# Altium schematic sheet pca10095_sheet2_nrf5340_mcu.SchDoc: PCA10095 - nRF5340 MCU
size A3; Organization: Nordic Semiconductor; DocumentNumber: 2; SheetNumber: 2; SheetTotal: 6; CompanyName: Nordic Semiconductor
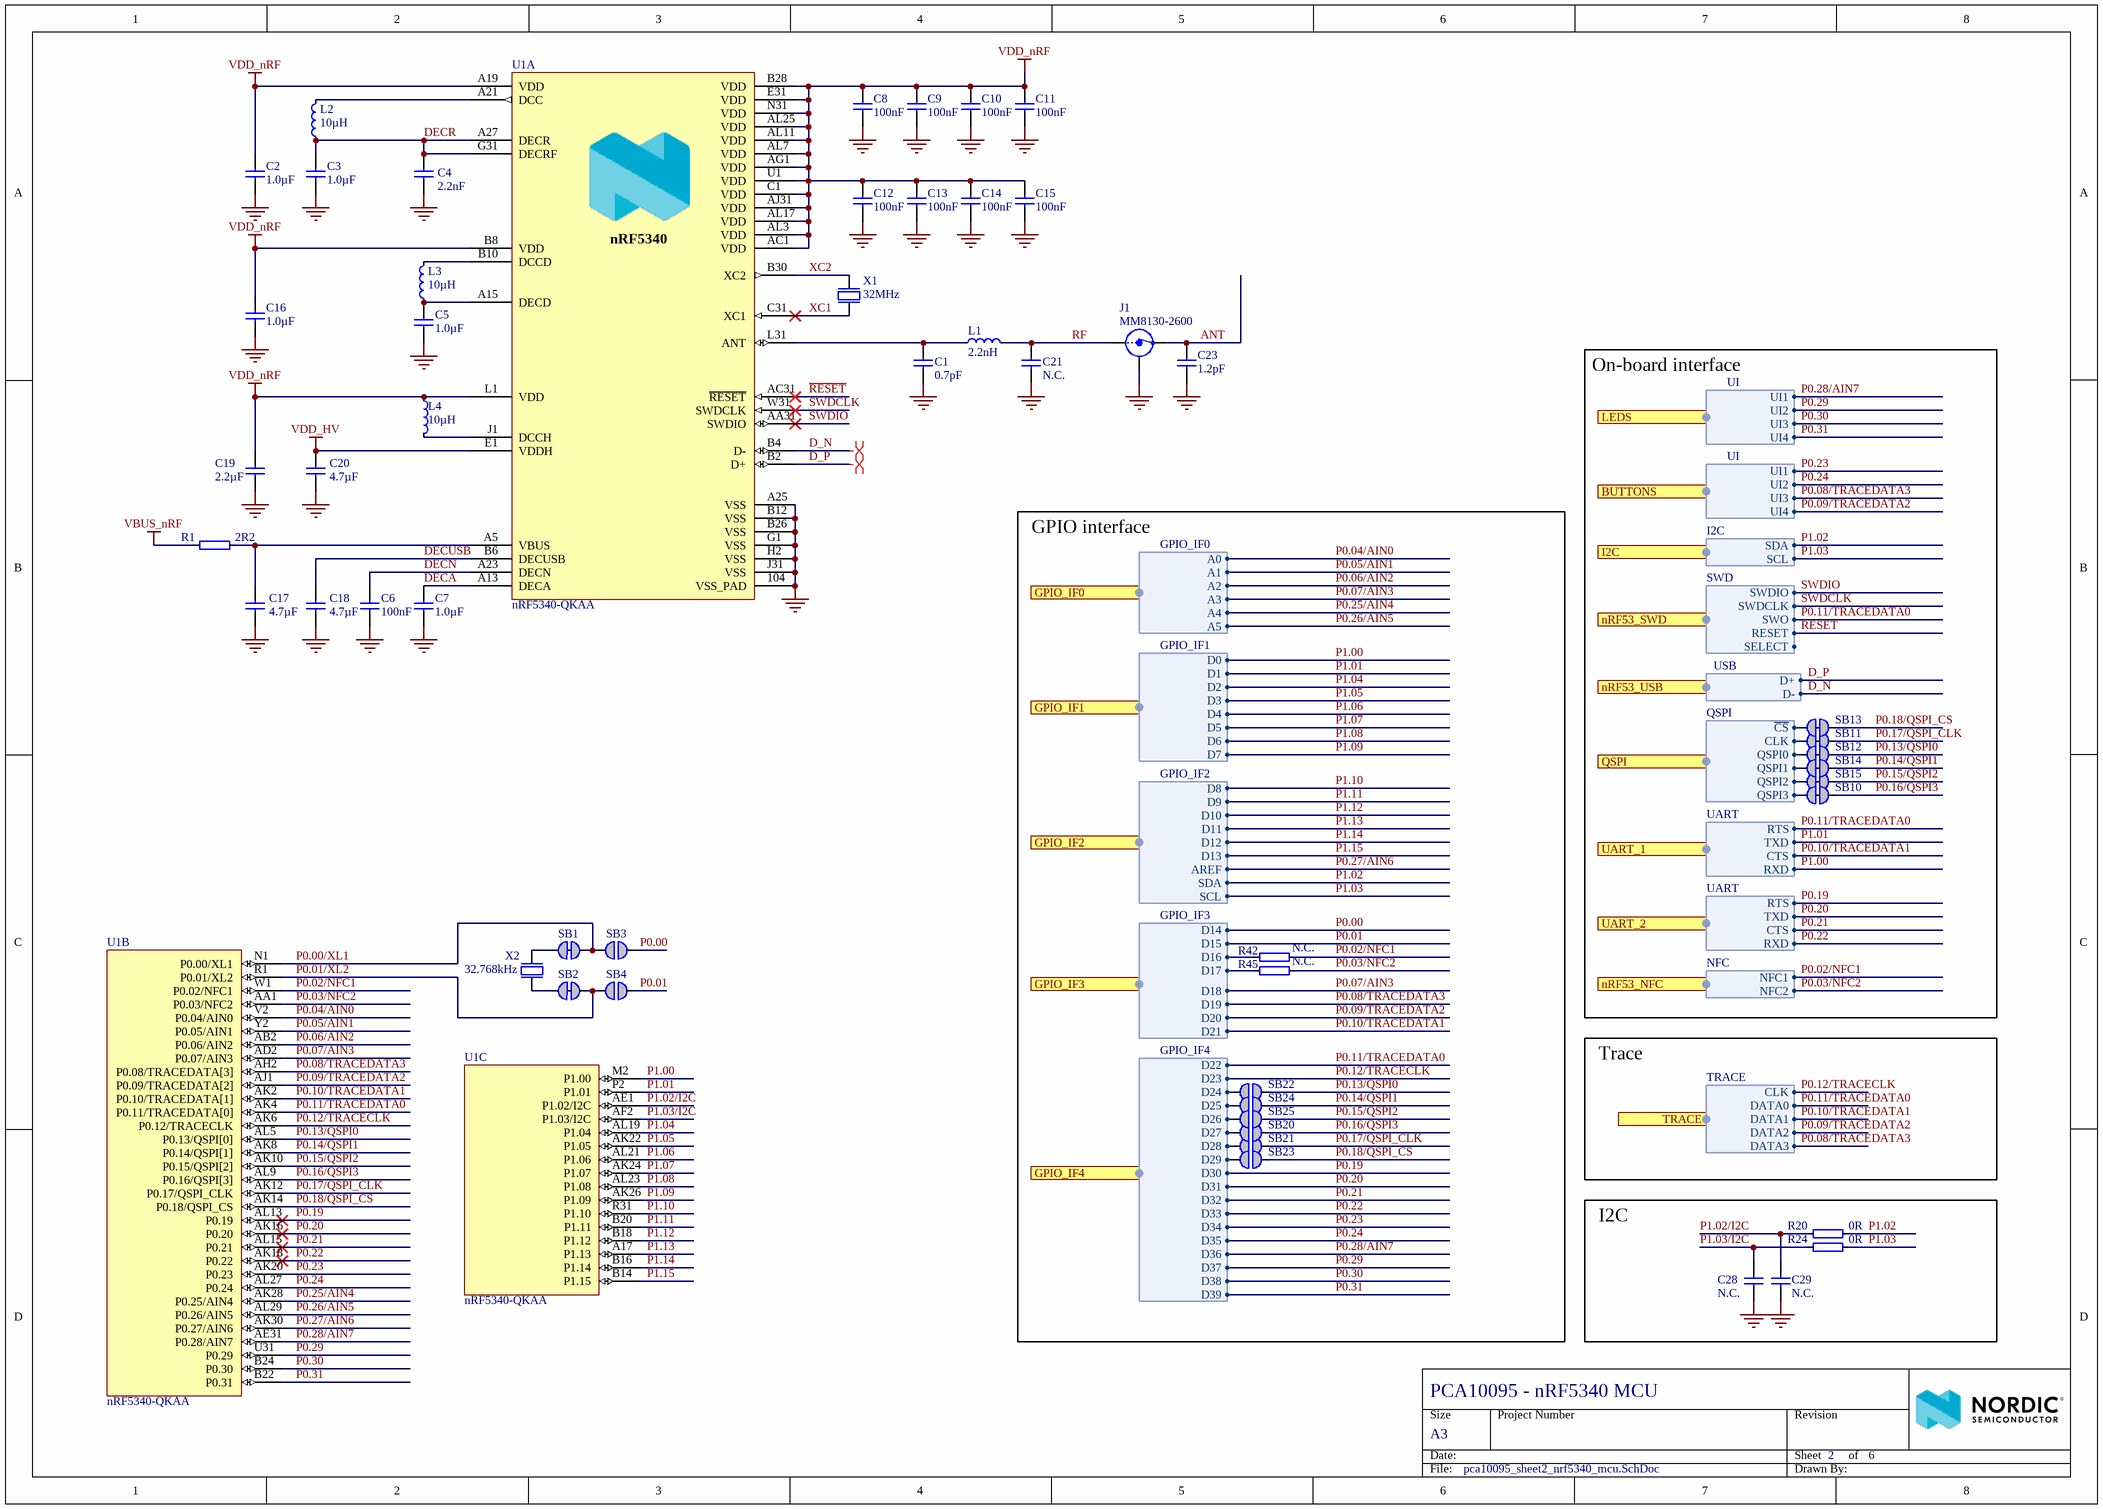
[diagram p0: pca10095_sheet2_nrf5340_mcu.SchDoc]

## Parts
C1  0.7pF  [CAPC0603X03L_C]
C2  1.0µF  [CAPC1005X04L]
C3  1.0µF  [CAPC1005X04L]
C4  2.2nF  [CAPC0603X03L_C]
C5  1.0µF  [CAPC1005X04L]
C6  100nF  [CAPC0603X03L_C]
C7  1.0µF  [CAPC1005X04L]
C8  100nF  [CAPC0603X03L_C]
C9  100nF  [CAPC0603X03L_C]
C10  100nF  [CAPC0603X03L_C]
C11  100nF  [CAPC0603X03L_C]
C12  100nF  [CAPC0603X03L_C]
C13  100nF  [CAPC0603X03L_C]
C14  100nF  [CAPC0603X03L_C]
C15  100nF  [CAPC0603X03L_C]
C16  1.0µF  [CAPC1005X04L]
C17  4.7µF  [CAPC1608X06L]
C18  4.7µF  [CAPC1608X06L]
C19  2.2µF  [CAPC1608X06L]
C20  4.7µF  [CAPC1608X06L]
C21  N.C.  [CAPC0603X03L_C_NC]
C23  1.2pF  [CAPC1005X04L]
C28  N.C.  [CAPC0603X03L_C_NC]
C29  N.C.  [CAPC0603X03L_C_NC]
J1  MM8130-2600  [COAXIAL-SWF]
L1  2.2nH  [INDC0603X03L_C]
L2  10µH  [INDC1608X06L]
L3  10µH  [INDC1608X06L]
L4  10µH  [INDC1608X06L]
R1  2R2  [RESC0603X03L_C]
R20  0R  [RESC0603X03L_C]
R24  0R  [RESC0603X03L_C]
R42  N.C.  [RESC0603X03L_C_NC]
R45  N.C.  [RESC0603X03L_C_NC]
SB1  Solderbridge  [Solderbridge_Shorted]  (value not drawn)  (net tie, no BOM)
SB2  Solderbridge  [Solderbridge_Shorted]  (value not drawn)  (net tie, no BOM)
SB3  Solderbridge  [Solderbridge]  (value not drawn)  (no BOM)
SB4  Solderbridge  [Solderbridge]  (value not drawn)  (no BOM)
SB10  Solderbridge  [Solderbridge_Shorted]  (value not drawn)  (net tie, no BOM)
SB11  Solderbridge  [Solderbridge_Shorted]  (value not drawn)  (net tie, no BOM)
SB12  Solderbridge  [Solderbridge_Shorted]  (value not drawn)  (net tie, no BOM)
SB13  Solderbridge  [Solderbridge_Shorted]  (value not drawn)  (net tie, no BOM)
SB14  Solderbridge  [Solderbridge_Shorted]  (value not drawn)  (net tie, no BOM)
SB15  Solderbridge  [Solderbridge_Shorted]  (value not drawn)  (net tie, no BOM)
SB20  Solderbridge  [Solderbridge]  (value not drawn)  (no BOM)
SB21  Solderbridge  [Solderbridge]  (value not drawn)  (no BOM)
SB22  Solderbridge  [Solderbridge]  (value not drawn)  (no BOM)
SB23  Solderbridge  [Solderbridge]  (value not drawn)  (no BOM)
SB24  Solderbridge  [Solderbridge]  (value not drawn)  (no BOM)
SB25  Solderbridge  [Solderbridge]  (value not drawn)  (no BOM)
U1  nRF5340-QKAA  [AQFN40P700X700X85_HS-99N]  (parts A,B,C of 3)
X1  32MHz  [BT-XTAL_2016]
X2  32.768kHz  [XTAL_2012]

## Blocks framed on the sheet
On-board interface: SB10-SB15
GPIO interface: R42 R45 SB20-SB25
I2C: C28 C29 R20 R24

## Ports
BUTTONS (harness UI), GPIO_IF0 (harness GPIO_IF0), GPIO_IF1 (harness GPIO_IF1), GPIO_IF2 (harness GPIO_IF2), GPIO_IF3 (harness GPIO_IF3), GPIO_IF4 (harness GPIO_IF4), I2C (harness I2C), LEDS (harness UI), nRF53_NFC (harness NFC), nRF53_SWD (harness SWD), nRF53_USB (harness USB), QSPI (harness QSPI), TRACE (harness TRACE), UART_1 (harness UART), UART_2 (harness UART)

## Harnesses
QSPI: ~{CS}, QSPI0, CLK, QSPI1, QSPI2, QSPI3
SWD: SWDIO, SWDCLK, SWO, RESET, SELECT
UI: UI4, UI3, UI2, UI1
USB: D+, D-
TRACE: CLK, DATA0, DATA1, DATA3, DATA2
NFC: NFC2, NFC1
UART: RTS, CTS, RXD, TXD
GPIO_IF1: D0, D1, D2, D3, D4, D5, D6, D7
GPIO_IF2: D8, D9, D10, D11, D12, D13, AREF, SDA, SCL
GPIO_IF0: A0, A1, A2, A3, A4, A5
GPIO_IF3: D14, D15, D16, D17, D18, D19, D20, D21
I2C: SCL, SDA
GPIO_IF4: D22, D23, D24, D25, D26, D27, D28, D29, D30, D31, D32, D33, D34, D35, D36, D37, D38, D39

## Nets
GND: C1.1 C2.2 C3.1 C4.2 C5.1 C6.2 C7.1 C8.2 C9.2 C10.2 C11.2 C12.2 C13.2 C14.2 C15.2 C16.1 C17.2 C18.2 C19.2 C20.2 C21.1 C23.2 C28.1 C29.1 J1.2(Shield) U1.104(VSS_PAD) U1.A25(VSS) U1.B12(VSS) U1.B26(VSS) U1.G1(VSS) U1.H2(VSS) U1.J31(VSS) X1.2(GND) X1.4(GND)
VBUS_nRF: R1.1
VDD_HV: C20.1 U1.E1(VDDH)
VDD_nRF: C2.1 C8.1 C9.1 C10.1 C11.1 C12.1 C13.1 C14.1 C15.1 C16.2 C19.1 L4.1 U1.A19(VDD) U1.AC1(VDD) U1.AG1(VDD) U1.AJ31(VDD) U1.AL3(VDD) U1.AL7(VDD) U1.AL11(VDD) U1.AL17(VDD) U1.AL25(VDD) U1.B8(VDD) U1.B28(VDD) U1.C1(VDD) U1.E31(VDD) U1.L1(VDD) U1.N31(VDD) U1.U1(VDD)
ANT: C23.1 J1.3(OUT)
D_N: U1.B4(D-) ; port nRF53_USB.D-
D_P: U1.B2(D+) ; port nRF53_USB.D+
DECA: C7.2 U1.A13(DECA)
DECN: C6.1 U1.A23(DECN)
DECR: C3.2 C4.1 L2.1 U1.A27(DECR) U1.G31(DECRF)
DECUSB: C18.1 U1.B6(DECUSB)
P0.00: SB3.2 ; port GPIO_IF3.D14
P0.00/XL1: SB1.2 SB3.1 U1.N1(P0.00/XL1)
P0.01: SB4.2 ; port GPIO_IF3.D15
P0.01/XL2: SB2.2 SB4.1 U1.R1(P0.01/XL2)
P0.02/NFC1: R42.2 U1.W1(P0.02/NFC1) ; port nRF53_NFC.NFC1
P0.03/NFC2: R45.2 U1.AA1(P0.03/NFC2) ; port nRF53_NFC.NFC2
P0.04/AIN0: U1.V2(P0.04/AIN0) ; port GPIO_IF0.A0
P0.05/AIN1: U1.Y2(P0.05/AIN1) ; port GPIO_IF0.A1
P0.06/AIN2: U1.AB2(P0.06/AIN2) ; port GPIO_IF0.A2
P0.07/AIN3: U1.AD2(P0.07/AIN3) ; port GPIO_IF0.A3, port GPIO_IF3.D18
P0.08/TRACEDATA3: U1.AH2(P0.08/TRACEDATA[3]) ; port BUTTONS.UI3, port TRACE.DATA3, port GPIO_IF3.D19
P0.09/TRACEDATA2: U1.AJ1(P0.09/TRACEDATA[2]) ; port BUTTONS.UI4, port TRACE.DATA2, port GPIO_IF3.D20
P0.10/TRACEDATA1: U1.AK2(P0.10/TRACEDATA[1]) ; port TRACE.DATA1, port GPIO_IF3.D21, port UART_1.CTS
P0.11/TRACEDATA0: U1.AK4(P0.11/TRACEDATA[0]) ; port nRF53_SWD.SWO, port TRACE.DATA0, port GPIO_IF4.D22, port UART_1.RTS
P0.12/TRACECLK: U1.AK6(P0.12/TRACECLK) ; port TRACE.CLK, port GPIO_IF4.D23
P0.13/QSPI0: SB12.1 SB22.1 U1.AL5(P0.13/QSPI[0])
P0.14/QSPI1: SB14.1 SB24.1 U1.AK8(P0.14/QSPI[1])
P0.15/QSPI2: SB15.1 SB25.1 U1.AK10(P0.15/QSPI[2])
P0.16/QSPI3: SB10.1 SB20.1 U1.AL9(P0.16/QSPI[3])
P0.17/QSPI_CLK: SB11.1 SB21.1 U1.AK12(P0.17/QSPI_CLK)
P0.18/QSPI_CS: SB13.1 SB23.1 U1.AK14(P0.18/QSPI_CS)
P0.19: U1.AL13(P0.19) ; port UART_2.RTS, port GPIO_IF4.D30
P0.20: U1.AK16(P0.20) ; port UART_2.TXD, port GPIO_IF4.D31
P0.21: U1.AL15(P0.21) ; port UART_2.CTS, port GPIO_IF4.D32
P0.22: U1.AK18(P0.22) ; port UART_2.RXD, port GPIO_IF4.D33
P0.23: U1.AK20(P0.23) ; port BUTTONS.UI1, port GPIO_IF4.D34
P0.24: U1.AL27(P0.24) ; port BUTTONS.UI2, port GPIO_IF4.D35
P0.25/AIN4: U1.AK28(P0.25/AIN4) ; port GPIO_IF0.A4
P0.26/AIN5: U1.AL29(P0.26/AIN5) ; port GPIO_IF0.A5
P0.27/AIN6: U1.AK30(P0.27/AIN6) ; port GPIO_IF2.AREF
P0.28/AIN7: U1.AE31(P0.28/AIN7) ; port LEDS.UI1, port GPIO_IF4.D36
P0.29: U1.U31(P0.29) ; port LEDS.UI2, port GPIO_IF4.D37
P0.30: U1.B24(P0.30) ; port LEDS.UI3, port GPIO_IF4.D38
P0.31: U1.B22(P0.31) ; port LEDS.UI4, port GPIO_IF4.D39
P1.00: U1.M2(P1.00) ; port GPIO_IF1.D0, port UART_1.RXD
P1.01: U1.P2(P1.01) ; port GPIO_IF1.D1, port UART_1.TXD
P1.02: R20.1 ; port GPIO_IF2.SDA, port I2C.SDA
P1.02/I2C: C29.2 R20.2 U1.AE1(P1.02/I2C)
P1.03: R24.1 ; port GPIO_IF2.SCL, port I2C.SCL
P1.03/I2C: C28.2 R24.2 U1.AF2(P1.03/I2C)
P1.04: U1.AL19(P1.04) ; port GPIO_IF1.D2
P1.05: U1.AK22(P1.05) ; port GPIO_IF1.D3
P1.06: U1.AL21(P1.06) ; port GPIO_IF1.D4
P1.07: U1.AK24(P1.07) ; port GPIO_IF1.D5
P1.08: U1.AL23(P1.08) ; port GPIO_IF1.D6
P1.09: U1.AK26(P1.09) ; port GPIO_IF1.D7
P1.10: U1.R31(P1.10) ; port GPIO_IF2.D8
P1.11: U1.B20(P1.11) ; port GPIO_IF2.D9
P1.12: U1.B18(P1.12) ; port GPIO_IF2.D10
P1.13: U1.A17(P1.13) ; port GPIO_IF2.D11
P1.14: U1.B16(P1.14) ; port GPIO_IF2.D12
P1.15: U1.B14(P1.15) ; port GPIO_IF2.D13
~{RESET}: U1.AC31(~{RESET}) ; port nRF53_SWD.RESET
RF: C21.2 J1.1(IN) L1.2
SWDCLK: U1.W31(SWDCLK) ; port nRF53_SWD.SWDCLK
SWDIO: U1.AA31(SWDIO) ; port nRF53_SWD.SWDIO
XC1: U1.C31(XC1) X1.1(inp)
XC2: U1.B30(XC2) X1.3(out)
NetC1_2: C1.2 L1.1 U1.L31(ANT)
NetC5_2: C5.2 L3.1 U1.A15(DECD)
NetC17_1: C17.1 R1.2 U1.A5(VBUS)
NetL2_2: L2.2 U1.A21(DCC)
NetL3_2: L3.2 U1.B10(DCCD)
NetL4_2: L4.2 U1.J1(DCCH)
NetR42_1: R42.1 ; port GPIO_IF3.D16
NetR45_1: R45.1 ; port GPIO_IF3.D17
NetSB1_1: SB1.1 X2.1(inp)
NetSB2_1: SB2.1 X2.2(out)
NetSB10_2: SB10.2 ; port QSPI.QSPI3
NetSB11_2: SB11.2 ; port QSPI.CLK
NetSB12_2: SB12.2 ; port QSPI.QSPI0
NetSB13_2: SB13.2 ; port QSPI.~{CS}
NetSB14_2: SB14.2 ; port QSPI.QSPI1
NetSB15_2: SB15.2 ; port QSPI.QSPI2
NetSB20_2: SB20.2 ; port GPIO_IF4.D27
NetSB21_2: SB21.2 ; port GPIO_IF4.D28
NetSB22_2: SB22.2 ; port GPIO_IF4.D24
NetSB23_2: SB23.2 ; port GPIO_IF4.D29
NetSB24_2: SB24.2 ; port GPIO_IF4.D25
NetSB25_2: SB25.2 ; port GPIO_IF4.D26

Not connected (* = marked no-connect by the designer): U1 AG31(N.C.) D2(N.C.) F2(N.C.) T2(N.C.)

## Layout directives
differential pair: D_N, D_P

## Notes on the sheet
- Trace

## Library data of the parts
C1 = C0201-0.7p-HQ-Murata: Ceramic Capacitor C0G, NP0 0201, ±0.1pF 25V; Manufacturer: Murata; Manufacturer Part Number: GJM0335C1ER70BB01D; Artikkelnr Noca: N.A.; Pad Count: 2
C2 C3 C5 C7 C16 = C0402-1µ0: Capacitor, X5R, ±5%, 6.3V; Manufacturer: N.A.; Part number IPS: 00000007786, 00000003457; Artikkelnr Noca: 20039235; Pad Count: 2
C4 = C0201-2n2: Capacitor, X7R, ±10%, 10V; Manufacturer: N.A.; Part number IPS: 00000001778; Pad Count: 2
C6 C8-C15 = C0201-100n: Capacitor, X5R, ±10%; Manufacturer: N.A.; Part number IPS: 00000001248, 00000002505; Note: 16V; Pad Count: 2
C17 C18 C20 = C0603-4µ7-10V-X7S: Capacitor, X7S, ±10%, 10V; Manufacturer: N.A.; Part number IPS: 00000001779; Artikkelnr Noca: 20030013; Pad Count: 2
C19 = C0603-2µ2: Capacitor, X7R, ±10%; Manufacturer: N.A.; Note: 6.3V; Artikkelnr Noca: 20039322; Pad Count: 2
C21 = C0201-N.C.: Not mounted; Manufacturer: N.A.; Note: Chip Cap; Assembly: Not mounted; Pad Count: 2
C23 = C0402-1.2p: Capacitor, NP0, ±0.1pF; Manufacturer: N.A.; Part number IPS: 00000005410; Note: 50V; Artikkelnr Noca: 20029157; Pad Count: 2
C28 C29 = C0201-N.C.: Not mounted; Manufacturer: N.A.; Assembly: Not mounted; Note: Chip Cap; Pad Count: 2
J1 = MM8130-2600: Coaxial Connector with Switch; Manufacturer: Murata; Part number IPS: 00000009955; Note: N.A.; Artikkelnr Noca: 55029011; Pad Count: 3
L1 = L0201-2n2-0.1nH: FIXED IND 2.2NH 600MA 120 MOHM; Manufacturer: Murata; Manufacturer Part Number: LQP03HQ2N2B02D; Note: High frequency chip inductor ±5%; Artikkelnr Noca: N.A.; Pad Count: 2
L2-L4 = L0603-10µ-TDK: Inductor, 250mA, ±20%, 1.05ohm. -55°C ~ 125°C; Manufacturer: TDK Corporation; Manufacturer Part Number: MLZ1608M100WTD25; Note: N.A.; Pad Count: 2
R1 = R0201-2R2: Resistor, ±1%, 0.05W; Manufacturer: N.A.; Note: Chip Res 1%; Pad Count: 2
R20 R24 = R0201-0R: Resistor, ±5%, 0.05W; Manufacturer: N.A.; Part number IPS: 00000003245; Note: Chip Res 5%; Pad Count: 2
R42 R45 = R0201-N.C.: Not mounted; Manufacturer: N.A.; Note: Chip Res; Assembly: Not mounted; Pad Count: 2
SB1 SB2 SB10-SB15 = Solderbridge Shorted: Shorted Solderbridge; Manufacturer: N.A.; Pad Count: 2
SB3 SB4 SB20-SB25 = Solderbridge: Manufacturer: N.A.; Pad Count: 2
U1 = nRF5340-QKAAD0: Multi-protocol Bluetooth Low Energy, IEEE 802.15.4, ANT and 2.4GHz proprietary system-on-chip; Manufacturer: Nordic Semiconductor; Note: N.A.; Pad Count: 98
X1 = XTAL_SMD2016_32MHz_8pF_Golledge: XTAL SMD 2016, 32MHz, Cl=8pF, Tol: ±10ppm, Stab: ±15ppm; Manufacturer Part Number: MP06003; Part number IPS: 00000001431; Note: XTAL SMD 32.000MHz; Artikkelnr Noca: 22010050; Pad Count: 4
X2 = XTAL_SMD2012_32.768kHz_9pF_Golledge: XTAL SMD 2012, 32.768kHz, 9pF, ±20ppm; Manufacturer Part Number: MP07668; Note: XTAL SMD 32.768kHz; Artikkelnr Noca: N.A.; Pad Count: 2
